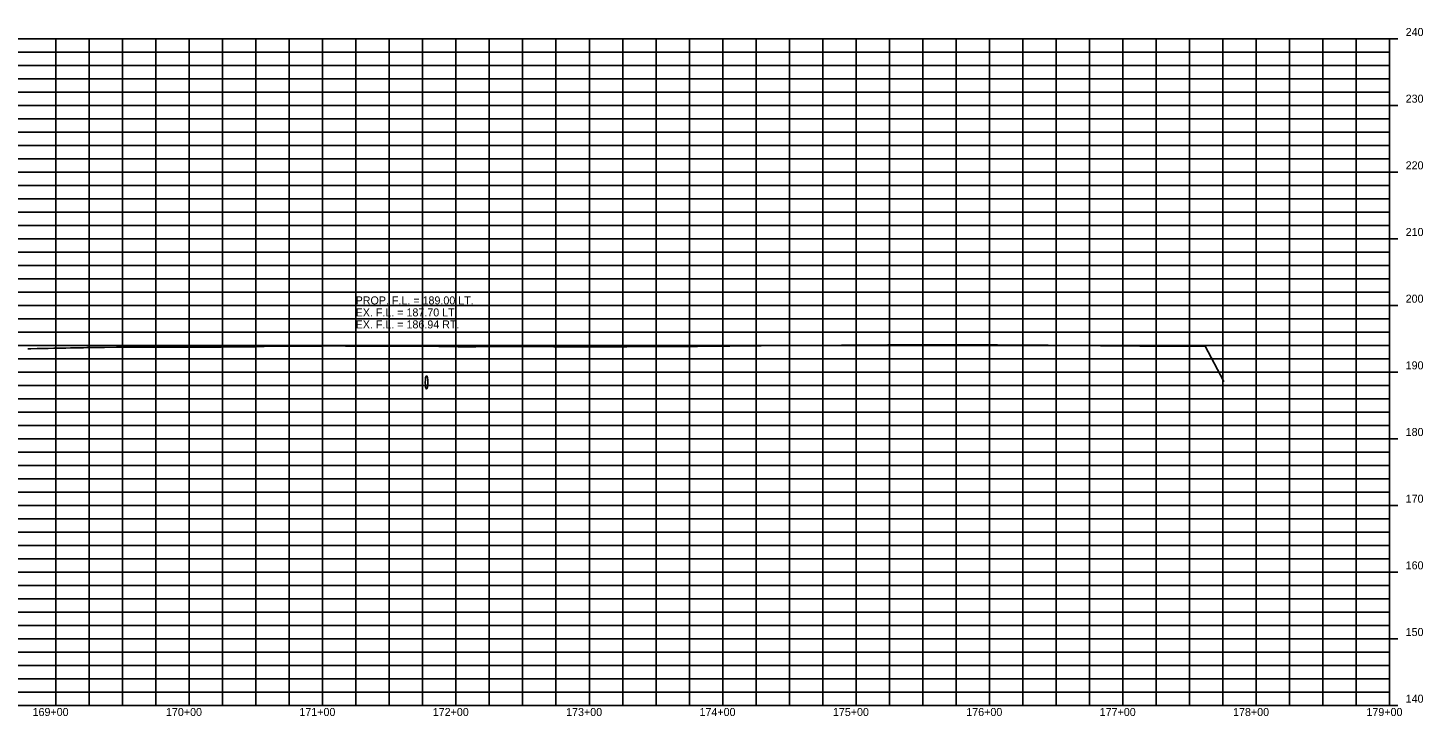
# Model space of a CAD drawing. Extents: x 1399671 to 1408349, y 1930471 to 1933387.
# Drawn here: x 1407203 to 1408249, y 1932871 to 1933387 of the extents above; entities that cross this region are included whole.
import ezdxf

# ---------------------------------------------------------------- set-up
doc = ezdxf.new("R2010")
doc.units = 0
for name, color, linetype in [('R_Drainage', 7, 'Continuous'), ('R_Exist Surface', 7, 'Continuous'), ('R_Grid', 7, 'Continuous'), ('R_Grid Annot', 7, 'Continuous'), ('R_Vert Alg Annot', 7, 'Continuous')]:
    doc.layers.add(name, color=color, linetype=linetype)

msp = doc.modelspace()

# ---------------------------------------------------------------- linework, layer by layer
at = {"layer": 'R_Drainage'}
msp.add_ellipse((1407502.2, 1933120.8), major_axis=(0, 5), ratio=0.2, dxfattribs=at)
at = {"layer": 'R_Exist Surface'}
msp.add_lwpolyline([(1407203.2, 1933145.9), (1407205.4, 1933146), (1407210.3, 1933146.2), (1407218.6, 1933146.3), (1407222.8, 1933146.4), (1407225.3, 1933146.5), (1407231.8, 1933146.6), (1407235.2, 1933146.7), (1407245, 1933146.8), (1407247.5, 1933146.9), (1407247.5, 1933146.9), (1407258.2, 1933147.1), (1407260.7, 1933147.1), (1407269.6, 1933147.2), (1407276.4, 1933147.3), (1407277.6, 1933147.3), (1407277.8, 1933147.3), (1407291.7, 1933147.3), (1407294.6, 1933147.3), (1407297.3, 1933147.3), (1407299.5, 1933147.3), (1407310.1, 1933147.3), (1407313.6, 1933147.3), (1407313.9, 1933147.3), (1407322.8, 1933147.3), (1407327.8, 1933147.2), (1407335.5, 1933147.2), (1407336, 1933147.2), (1407342.1, 1933147.2), (1407348.2, 1933147.2), (1407358.1, 1933147.4), (1407363.9, 1933147.5), (1407369.8, 1933147.6), (1407373.8, 1933147.6), (1407380.3, 1933147.7), (1407391.6, 1933147.9), (1407391.7, 1933147.9), (1407392.6, 1933147.9), (1407402.4, 1933148), (1407414.8, 1933148), (1407415.5, 1933148), (1407416.3, 1933148), (1407424.5, 1933148.1), (1407439.3, 1933148.2), (1407441.3, 1933148.1), (1407446.7, 1933148.1), (1407463.6, 1933148.1), (1407468.2, 1933148.1), (1407482.5, 1933148.1), (1407487.9, 1933148.1), (1407489.8, 1933148.1), (1407500.7, 1933147.9), (1407506.9, 1933147.9), (1407511.4, 1933147.8), (1407518, 1933147.7), (1407525.9, 1933147.6), (1407532.9, 1933147.6), (1407539.1, 1933147.6), (1407550.5, 1933147.7), (1407554.5, 1933147.7), (1407562.5, 1933147.7), (1407575.1, 1933147.7), (1407576.1, 1933147.7), (1407585.1, 1933147.7), (1407597.6, 1933147.6), (1407599.2, 1933147.6), (1407607.7, 1933147.6), (1407619.2, 1933147.5), (1407623.3, 1933147.5), (1407627.3, 1933147.5), (1407636.1, 1933147.6), (1407639.7, 1933147.6), (1407640.7, 1933147.6), (1407648.9, 1933147.6), (1407652.2, 1933147.6), (1407661.6, 1933147.7), (1407662.3, 1933147.7), (1407664.6, 1933147.7), (1407674.3, 1933147.7), (1407677, 1933147.7), (1407683.9, 1933147.8), (1407687.1, 1933147.8), (1407689.6, 1933147.8), (1407699.9, 1933147.8), (1407702.2, 1933147.8), (1407705.4, 1933147.8), (1407712.7, 1933147.9), (1407714.9, 1933147.9), (1407725.5, 1933147.9), (1407727, 1933147.9), (1407729.6, 1933148), (1407748.6, 1933148.2), (1407749.9, 1933148.2), (1407753.1, 1933148.2), (1407770.1, 1933148.4), (1407774.2, 1933148.5), (1407791.7, 1933148.6), (1407797.1, 1933148.6), (1407798.8, 1933148.6), (1407813.2, 1933148.7), (1407822.5, 1933148.8), (1407823.5, 1933148.8), (1407824.4, 1933148.8), (1407834.8, 1933148.8), (1407848.1, 1933148.9), (1407848.9, 1933148.9), (1407856.4, 1933148.9), (1407872.7, 1933149), (1407873.6, 1933149), (1407877.9, 1933149), (1407894.7, 1933149), (1407895.3, 1933149), (1407899.5, 1933149), (1407916.8, 1933149), (1407916.9, 1933149), (1407921.1, 1933149), (1407929.6, 1933148.9), (1407929.6, 1933148.9), (1407930.1, 1933148.9), (1407942.4, 1933148.8), (1407942.5, 1933148.8), (1407942.6, 1933148.8), (1407955.2, 1933148.8), (1407955.4, 1933148.8), (1407964.2, 1933148.7), (1407967.9, 1933148.7), (1407968.2, 1933148.7), (1407981, 1933148.6), (1407981.3, 1933148.6), (1407981.5, 1933148.6), (1407994.3, 1933148.4), (1407994.5, 1933148.4), (1408007.4, 1933148.3), (1408007.6, 1933148.3), (1408020.4, 1933148.2), (1408020.6, 1933148.2), (1408036.8, 1933148.1), (1408036.9, 1933148.1), (1408053.1, 1933148.1), (1408053.2, 1933148.1), (1408063.3, 1933148), (1408069.5, 1933148), (1408069.5, 1933148), (1408085.8, 1933147.9), (1408085.9, 1933147.9), (1408085.9, 1933147.9), (1408099.7, 1933122), (1408100.1, 1933121.6)], dxfattribs=at)
at = {"layer": 'R_Grid'}
for p, q in [((1400324.2, 1933378.6), (1408224.2, 1933378.6)), ((1400324.2, 1933378.6), (1408224.2, 1933378.6)), ((1407224.2, 1932878.6), (1407224.2, 1933378.6)), ((1407249.2, 1932878.6), (1407249.2, 1933378.6)), ((1407274.2, 1932878.6), (1407274.2, 1933378.6)), ((1407299.2, 1932878.6), (1407299.2, 1933378.6)), ((1407324.2, 1932878.6), (1407324.2, 1933378.6)), ((1407349.2, 1932878.6), (1407349.2, 1933378.6)), ((1407374.2, 1932878.6), (1407374.2, 1933378.6)), ((1407399.2, 1932878.6), (1407399.2, 1933378.6)), ((1407424.2, 1932878.6), (1407424.2, 1933378.6)), ((1407449.2, 1932878.6), (1407449.2, 1933378.6)), ((1407474.2, 1932878.6), (1407474.2, 1933378.6)), ((1407499.2, 1932878.6), (1407499.2, 1933378.6)), ((1407524.2, 1932878.6), (1407524.2, 1933378.6)), ((1407549.2, 1932878.6), (1407549.2, 1933378.6)), ((1407574.2, 1932878.6), (1407574.2, 1933378.6)), ((1407599.2, 1932878.6), (1407599.2, 1933378.6)), ((1407624.2, 1932878.6), (1407624.2, 1933378.6)), ((1407649.2, 1932878.6), (1407649.2, 1933378.6)), ((1407674.2, 1932878.6), (1407674.2, 1933378.6)), ((1407699.2, 1932878.6), (1407699.2, 1933378.6)), ((1407724.2, 1932878.6), (1407724.2, 1933378.6)), ((1407749.2, 1932878.6), (1407749.2, 1933378.6)), ((1407774.2, 1932878.6), (1407774.2, 1933378.6)), ((1407799.2, 1932878.6), (1407799.2, 1933378.6)), ((1407824.2, 1932878.6), (1407824.2, 1933378.6)), ((1407849.2, 1932878.6), (1407849.2, 1933378.6)), ((1407874.2, 1932878.6), (1407874.2, 1933378.6)), ((1407899.2, 1932878.6), (1407899.2, 1933378.6)), ((1407924.2, 1932878.6), (1407924.2, 1933378.6)), ((1407949.2, 1932878.6), (1407949.2, 1933378.6)), ((1407974.2, 1932878.6), (1407974.2, 1933378.6)), ((1407999.2, 1932878.6), (1407999.2, 1933378.6)), ((1408024.2, 1932878.6), (1408024.2, 1933378.6)), ((1408049.2, 1932878.6), (1408049.2, 1933378.6)), ((1408074.2, 1932878.6), (1408074.2, 1933378.6)), ((1408099.2, 1932878.6), (1408099.2, 1933378.6)), ((1408124.2, 1932878.6), (1408124.2, 1933378.6)), ((1408149.2, 1932878.6), (1408149.2, 1933378.6)), ((1408174.2, 1932878.6), (1408174.2, 1933378.6)), ((1408199.2, 1932878.6), (1408199.2, 1933378.6)), ((1408224.2, 1932878.6), (1408224.2, 1933378.6)), ((1400324.2, 1933368.6), (1408224.2, 1933368.6)), ((1400324.2, 1933358.6), (1408224.2, 1933358.6)), ((1400324.2, 1933348.6), (1408224.2, 1933348.6)), ((1400324.2, 1933338.6), (1408224.2, 1933338.6)), ((1400324.2, 1933328.6), (1408224.2, 1933328.6)), ((1400324.2, 1933318.6), (1408224.2, 1933318.6)), ((1400324.2, 1933308.6), (1408224.2, 1933308.6)), ((1400324.2, 1933298.6), (1408224.2, 1933298.6)), ((1400324.2, 1933288.6), (1408224.2, 1933288.6)), ((1400324.2, 1933278.6), (1408224.2, 1933278.6)), ((1400324.2, 1933268.6), (1408224.2, 1933268.6)), ((1400324.2, 1933258.6), (1408224.2, 1933258.6)), ((1400324.2, 1933248.6), (1408224.2, 1933248.6)), ((1400324.2, 1933238.6), (1408224.2, 1933238.6)), ((1400324.2, 1933228.6), (1408224.2, 1933228.6)), ((1400324.2, 1933218.6), (1408224.2, 1933218.6)), ((1400324.2, 1933208.6), (1408224.2, 1933208.6)), ((1400324.2, 1933198.6), (1408224.2, 1933198.6)), ((1400324.2, 1933188.6), (1408224.2, 1933188.6)), ((1400324.2, 1933178.6), (1408224.2, 1933178.6)), ((1400324.2, 1933168.6), (1408224.2, 1933168.6)), ((1400324.2, 1933158.6), (1408224.2, 1933158.6)), ((1400324.2, 1933148.6), (1408224.2, 1933148.6)), ((1400324.2, 1933138.6), (1408224.2, 1933138.6)), ((1400324.2, 1933128.6), (1408224.2, 1933128.6)), ((1400324.2, 1933118.6), (1408224.2, 1933118.6)), ((1400324.2, 1933108.6), (1408224.2, 1933108.6)), ((1400324.2, 1933098.6), (1408224.2, 1933098.6)), ((1400324.2, 1933088.6), (1408224.2, 1933088.6)), ((1400324.2, 1933078.6), (1408224.2, 1933078.6)), ((1400324.2, 1933068.6), (1408224.2, 1933068.6)), ((1400324.2, 1933058.6), (1408224.2, 1933058.6)), ((1400324.2, 1933048.6), (1408224.2, 1933048.6)), ((1400324.2, 1933038.6), (1408224.2, 1933038.6)), ((1400324.2, 1933028.6), (1408224.2, 1933028.6)), ((1400324.2, 1933018.6), (1408224.2, 1933018.6)), ((1400324.2, 1933008.6), (1408224.2, 1933008.6)), ((1400324.2, 1932998.6), (1408224.2, 1932998.6)), ((1400324.2, 1932988.6), (1408224.2, 1932988.6)), ((1400324.2, 1932978.6), (1408224.2, 1932978.6)), ((1400324.2, 1932968.6), (1408224.2, 1932968.6)), ((1400324.2, 1932958.6), (1408224.2, 1932958.6)), ((1400324.2, 1932948.6), (1408224.2, 1932948.6)), ((1400324.2, 1932938.6), (1408224.2, 1932938.6)), ((1400324.2, 1932928.6), (1408224.2, 1932928.6)), ((1400324.2, 1932918.6), (1408224.2, 1932918.6)), ((1400324.2, 1932908.6), (1408224.2, 1932908.6)), ((1400324.2, 1932898.6), (1408224.2, 1932898.6)), ((1400324.2, 1932888.6), (1408224.2, 1932888.6)), ((1400324.2, 1932878.6), (1408224.2, 1932878.6))]:
    msp.add_line(p, q, dxfattribs=at)
at = {"layer": 'R_Grid Annot'}
for p, q in [((1408230.2, 1933378.6), (1408224.2, 1933378.6)), ((1408230.2, 1933378.6), (1408224.2, 1933378.6)), ((1408224.2, 1933368.6), (1408221.2, 1933368.6)), ((1408224.2, 1933358.6), (1408221.2, 1933358.6)), ((1408224.2, 1933348.6), (1408221.2, 1933348.6)), ((1408224.2, 1933338.6), (1408221.2, 1933338.6)), ((1408230.2, 1933328.6), (1408224.2, 1933328.6)), ((1408224.2, 1933318.6), (1408221.2, 1933318.6)), ((1408224.2, 1933308.6), (1408221.2, 1933308.6)), ((1408224.2, 1933298.6), (1408221.2, 1933298.6)), ((1408224.2, 1933288.6), (1408221.2, 1933288.6)), ((1408230.2, 1933278.6), (1408224.2, 1933278.6)), ((1408224.2, 1933268.6), (1408221.2, 1933268.6)), ((1408224.2, 1933258.6), (1408221.2, 1933258.6)), ((1408224.2, 1933248.6), (1408221.2, 1933248.6)), ((1408224.2, 1933238.6), (1408221.2, 1933238.6)), ((1408230.2, 1933228.6), (1408224.2, 1933228.6)), ((1408224.2, 1933218.6), (1408221.2, 1933218.6)), ((1408224.2, 1933208.6), (1408221.2, 1933208.6)), ((1408224.2, 1933198.6), (1408221.2, 1933198.6)), ((1408224.2, 1933188.6), (1408221.2, 1933188.6)), ((1408230.2, 1933178.6), (1408224.2, 1933178.6)), ((1408224.2, 1933168.6), (1408221.2, 1933168.6)), ((1408224.2, 1933158.6), (1408221.2, 1933158.6)), ((1408224.2, 1933148.6), (1408221.2, 1933148.6)), ((1408224.2, 1933138.6), (1408221.2, 1933138.6)), ((1408230.2, 1933128.6), (1408224.2, 1933128.6)), ((1408224.2, 1933118.6), (1408221.2, 1933118.6)), ((1408224.2, 1933108.6), (1408221.2, 1933108.6)), ((1408224.2, 1933098.6), (1408221.2, 1933098.6)), ((1408224.2, 1933088.6), (1408221.2, 1933088.6)), ((1408224.2, 1933068.6), (1408221.2, 1933068.6)), ((1408230.2, 1933078.6), (1408224.2, 1933078.6)), ((1408224.2, 1933058.6), (1408221.2, 1933058.6)), ((1408224.2, 1933048.6), (1408221.2, 1933048.6)), ((1408224.2, 1933038.6), (1408221.2, 1933038.6)), ((1408230.2, 1933028.6), (1408224.2, 1933028.6)), ((1408224.2, 1933018.6), (1408221.2, 1933018.6)), ((1408224.2, 1933008.6), (1408221.2, 1933008.6)), ((1408224.2, 1932998.6), (1408221.2, 1932998.6)), ((1408224.2, 1932988.6), (1408221.2, 1932988.6)), ((1408230.2, 1932978.6), (1408224.2, 1932978.6)), ((1408224.2, 1932968.6), (1408221.2, 1932968.6)), ((1408224.2, 1932958.6), (1408221.2, 1932958.6)), ((1408224.2, 1932948.6), (1408221.2, 1932948.6)), ((1408224.2, 1932938.6), (1408221.2, 1932938.6)), ((1408230.2, 1932928.6), (1408224.2, 1932928.6)), ((1408224.2, 1932918.6), (1408221.2, 1932918.6)), ((1408224.2, 1932908.6), (1408221.2, 1932908.6)), ((1408224.2, 1932898.6), (1408221.2, 1932898.6)), ((1408224.2, 1932888.6), (1408221.2, 1932888.6)), ((1408230.2, 1932878.6), (1408224.2, 1932878.6))]:
    msp.add_line(p, q, dxfattribs=at)

# ---------------------------------------------------------------- texts
for s, p in [('240', (1408236.2, 1933380.6)), ('240', (1408236.2, 1933380.6)), ('230', (1408236.2, 1933330.6)), ('220', (1408236.2, 1933280.6)), ('210', (1408236.2, 1933230.6)), ('200', (1408236.2, 1933180.6)), ('190', (1408236.2, 1933130.6)), ('180', (1408236.2, 1933080.6)), ('170', (1408236.2, 1933030.6)), ('160', (1408236.2, 1932980.6)), ('150', (1408236.2, 1932930.6)), ('140', (1408236.2, 1932880.6)), ('169+00', (1407206.8, 1932870.6)), ('170+00', (1407306.8, 1932870.6)), ('171+00', (1407406.8, 1932870.6)), ('172+00', (1407506.8, 1932870.6)), ('173+00', (1407606.8, 1932870.6)), ('174+00', (1407706.8, 1932870.6)), ('175+00', (1407806.8, 1932870.6)), ('176+00', (1407906.8, 1932870.6)), ('177+00', (1408006.8, 1932870.6)), ('178+00', (1408106.8, 1932870.6)), ('179+00', (1408206.8, 1932870.6))]:
    msp.add_text(s, height=6, dxfattribs=at).set_placement(p)
at = {"layer": 'R_Vert Alg Annot'}
for s, p in [('PROP. F.L. = 189.00 LT.', (1407449, 1933179.3)), ('EX. F.L. = 187.70 LT.', (1407449, 1933170.3)), ('EX. F.L. = 186.94 RT.', (1407449, 1933161.3))]:
    msp.add_text(s, height=6, dxfattribs=at).set_placement(p)

doc.saveas('drawing.dxf')
